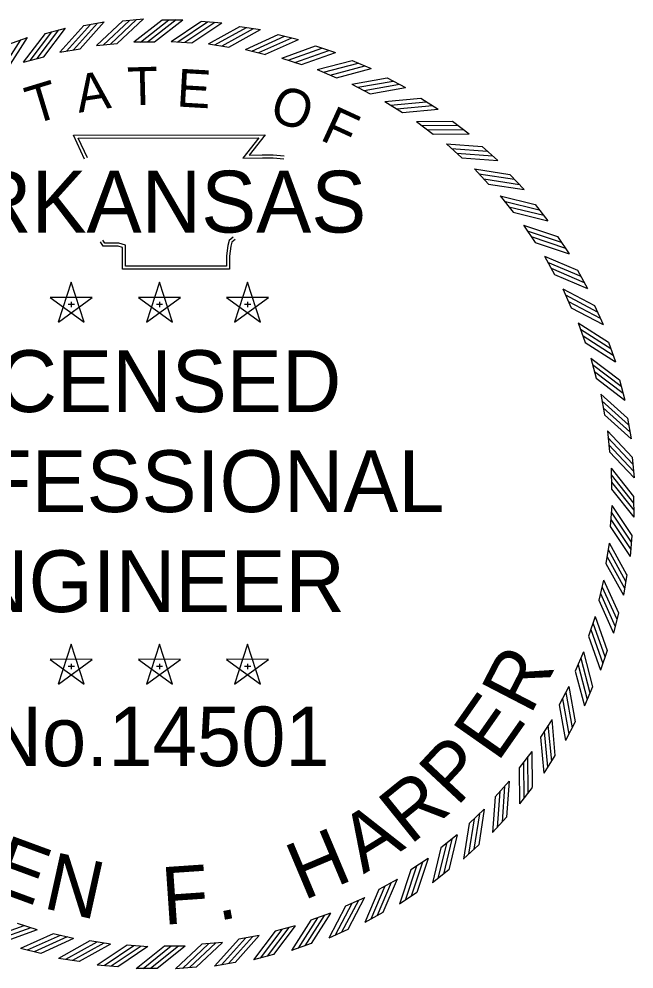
# Model space of a CAD drawing. Extents: x 16 to 1228740, y 11 to 152440.
# Drawn here: x 17.7474 to 17.8589, y 10.8144 to 10.9865 of the extents above; entities that cross this region are included whole.
import ezdxf

# ---------------------------------------------------------------- set-up
doc = ezdxf.new("R2010")
doc.units = 0
doc.layers.add('STAMP_FRED', color=7, linetype='Continuous')

msp = doc.modelspace()

# ---------------------------------------------------------------- linework, layer by layer
at = {"layer": 'STAMP_FRED'}
for p, q in [((17.75911, 10.98533), (17.76283, 10.98598)), ((17.76617, 10.98617), (17.76992, 10.98652)), ((17.77331, 10.98638), (17.77708, 10.98638)), ((17.78037, 10.9861), (17.78413, 10.98582)), ((17.75215, 10.9839), (17.7558, 10.98486)), ((17.78742, 10.98518), (17.79114, 10.9846)), ((17.74533, 10.98191), (17.74888, 10.98317)), ((17.79436, 10.98369), (17.79803, 10.9828)), ((17.75474, 10.98048), (17.75847, 10.98114)), ((17.76141, 10.9817), (17.76518, 10.98205)), ((17.76816, 10.98237), (17.77194, 10.98237)), ((17.77494, 10.98247), (17.77871, 10.9822)), ((17.78171, 10.98202), (17.78544, 10.98143)), ((17.78842, 10.98101), (17.79209, 10.98011)), ((17.80116, 10.98163), (17.80474, 10.98044)), ((17.7482, 10.97872), (17.75185, 10.97968)), ((17.79502, 10.97945), (17.7986, 10.97825)), ((17.80777, 10.97901), (17.81124, 10.97753)), ((17.80146, 10.97734), (17.80494, 10.97586)), ((17.81414, 10.97586), (17.81747, 10.97409)), ((17.80772, 10.97472), (17.81106, 10.97295)), ((17.81373, 10.97158), (17.81691, 10.96955)), ((17.82023, 10.97219), (17.8234, 10.97016)), ((17.81946, 10.96796), (17.82247, 10.96567)), ((17.82599, 10.96803), (17.82898, 10.96574)), ((17.82488, 10.96388), (17.82768, 10.96135)), ((17.83139, 10.96341), (17.83418, 10.96088)), ((17.82994, 10.95937), (17.83253, 10.95661)), ((17.83639, 10.95836), (17.83896, 10.95561)), ((17.83461, 10.95445), (17.83696, 10.95149)), ((17.84095, 10.95291), (17.84329, 10.94996)), ((17.83886, 10.94916), (17.84096, 10.94602)), ((17.84505, 10.94711), (17.84714, 10.94397)), ((17.84266, 10.94354), (17.84449, 10.94024)), ((17.84866, 10.94098), (17.85048, 10.93769)), ((17.75683, 10.93882), (17.75448, 10.93158)), ((17.75918, 10.93158), (17.75684, 10.93882)), ((17.77283, 10.93882), (17.77047, 10.93158)), ((17.77518, 10.93158), (17.77283, 10.93882)), ((17.78882, 10.93882), (17.78646, 10.93158)), ((17.79117, 10.93158), (17.78882, 10.93882)), ((17.76064, 10.93605), (17.75303, 10.93606)), ((17.77663, 10.93605), (17.76902, 10.93606)), ((17.79262, 10.93605), (17.78501, 10.93606)), ((17.84598, 10.93763), (17.84753, 10.93419)), ((17.75303, 10.93605), (17.75919, 10.93157)), ((17.75449, 10.93158), (17.76065, 10.93605)), ((17.75629, 10.93484), (17.75742, 10.93484)), ((17.75684, 10.93524), (17.75684, 10.93429)), ((17.76902, 10.93605), (17.77518, 10.93157)), ((17.77048, 10.93158), (17.77664, 10.93605)), ((17.77228, 10.93484), (17.77341, 10.93484)), ((17.77283, 10.93524), (17.77283, 10.93429)), ((17.78501, 10.93605), (17.79117, 10.93157)), ((17.78647, 10.93158), (17.79263, 10.93605)), ((17.78827, 10.93484), (17.78941, 10.93484)), ((17.78882, 10.93524), (17.78882, 10.93429)), ((17.85175, 10.93458), (17.85329, 10.93115)), ((17.8488, 10.93146), (17.85006, 10.9279)), ((17.85429, 10.92795), (17.85555, 10.9244)), ((17.8511, 10.92509), (17.85206, 10.92143)), ((17.85629, 10.92113), (17.85725, 10.91748)), ((17.85287, 10.91854), (17.85352, 10.91482)), ((17.85771, 10.91417), (17.85837, 10.91046)), ((17.85409, 10.91187), (17.85443, 10.9081)), ((17.85855, 10.90711), (17.8589, 10.90336)), ((17.85475, 10.90512), (17.85479, 10.90134)), ((17.85881, 10.90001), (17.85885, 10.89624)), ((17.85486, 10.89834), (17.85458, 10.89457)), ((17.8544, 10.89157), (17.85382, 10.88784)), ((17.85848, 10.89291), (17.8582, 10.88915)), ((17.85339, 10.88486), (17.8525, 10.88119)), ((17.85757, 10.88586), (17.85698, 10.88214)), ((17.85183, 10.87827), (17.85064, 10.87468)), ((17.85607, 10.87892), (17.85518, 10.87525)), ((17.75683, 10.87325), (17.75448, 10.86602)), ((17.75918, 10.86602), (17.75684, 10.87326)), ((17.77283, 10.87325), (17.77047, 10.86602)), ((17.77518, 10.86602), (17.77283, 10.87326)), ((17.78882, 10.87325), (17.78646, 10.86602)), ((17.79117, 10.86602), (17.78882, 10.87326)), ((17.84973, 10.87182), (17.84824, 10.86834)), ((17.85401, 10.87212), (17.85282, 10.86854)), ((17.76064, 10.87049), (17.75303, 10.8705)), ((17.75303, 10.87049), (17.75919, 10.86601)), ((17.75449, 10.86602), (17.76065, 10.87049)), ((17.75629, 10.86927), (17.75742, 10.86927)), ((17.75684, 10.86968), (17.75684, 10.86873)), ((17.77663, 10.87049), (17.76902, 10.8705)), ((17.76902, 10.87049), (17.77518, 10.86601)), ((17.77048, 10.86602), (17.77664, 10.87049)), ((17.77228, 10.86927), (17.77341, 10.86927)), ((17.77283, 10.86968), (17.77283, 10.86873)), ((17.79262, 10.87049), (17.78501, 10.8705)), ((17.78501, 10.87049), (17.79117, 10.86601)), ((17.78647, 10.86602), (17.79263, 10.87049)), ((17.78827, 10.86927), (17.78941, 10.86927)), ((17.78882, 10.86968), (17.78882, 10.86873)), ((17.8471, 10.86557), (17.84533, 10.86223)), ((17.85139, 10.86551), (17.84991, 10.86204)), ((17.84397, 10.85955), (17.84193, 10.85637)), ((17.84824, 10.85914), (17.84648, 10.85581)), ((17.84035, 10.85382), (17.83805, 10.85081)), ((17.84457, 10.85306), (17.84254, 10.84988)), ((17.83626, 10.8484), (17.83373, 10.8456)), ((17.84041, 10.84729), (17.83812, 10.8443)), ((17.83175, 10.84334), (17.82899, 10.84076)), ((17.83579, 10.84189), (17.83326, 10.8391)), ((17.82683, 10.83867), (17.82387, 10.83632)), ((17.83074, 10.8369), (17.82799, 10.83432)), ((17.82155, 10.83442), (17.8184, 10.83233)), ((17.8253, 10.83233), (17.82234, 10.82999)), ((17.81593, 10.83062), (17.81262, 10.8288)), ((17.81949, 10.82823), (17.81635, 10.82614)), ((17.81001, 10.8273), (17.80657, 10.82576)), ((17.80385, 10.82448), (17.80029, 10.82322)), ((17.81337, 10.82462), (17.81007, 10.8228)), ((17.75065, 10.82145), (17.74706, 10.82265)), ((17.75725, 10.81989), (17.75358, 10.82078)), ((17.79747, 10.82218), (17.79381, 10.82122)), ((17.80697, 10.82154), (17.80353, 10.81999)), ((17.76395, 10.81888), (17.76022, 10.81947)), ((17.78425, 10.81919), (17.78049, 10.81885)), ((17.79092, 10.82042), (17.7872, 10.81976)), ((17.7513, 10.81721), (17.74764, 10.8181)), ((17.77072, 10.81842), (17.76695, 10.8187)), ((17.7775, 10.81853), (17.77372, 10.81849)), ((17.80033, 10.81899), (17.79678, 10.81773)), ((17.75825, 10.81572), (17.75452, 10.8163)), ((17.78655, 10.81557), (17.78284, 10.81492)), ((17.79351, 10.81699), (17.78987, 10.81603)), ((17.7653, 10.8148), (17.76154, 10.81508)), ((17.77239, 10.81447), (17.76862, 10.81444)), ((17.7795, 10.81473), (17.77574, 10.81438))]:
    msp.add_line(p, q, dxfattribs=at)
for points in [[(17.75846, 10.98114), (17.76283, 10.98599)], [(17.76141, 10.9817), (17.76616, 10.98617)], [(17.76262, 10.9818), (17.76737, 10.98627)], [(17.76392, 10.98195), (17.76868, 10.98642)], [(17.76517, 10.98205), (17.76993, 10.98652)], [(17.76816, 10.98237), (17.7733, 10.98638)], [(17.76937, 10.98235), (17.77452, 10.98637)], [(17.77068, 10.98238), (17.77583, 10.9864)], [(17.77194, 10.98237), (17.77708, 10.98638)], [(17.77494, 10.98247), (17.78036, 10.98609)], [(17.77615, 10.98237), (17.78157, 10.98599)], [(17.75063, 10.97937), (17.75458, 10.98456)], [(17.75185, 10.97968), (17.7558, 10.98487)], [(17.75474, 10.98048), (17.75911, 10.98532)], [(17.75594, 10.98068), (17.76031, 10.98552)], [(17.75722, 10.98093), (17.76159, 10.98578)], [(17.77746, 10.9823), (17.78288, 10.98593)], [(17.77871, 10.9822), (17.78413, 10.98582)], [(17.78171, 10.98202), (17.78741, 10.98518)], [(17.7829, 10.98182), (17.78861, 10.98498)], [(17.7842, 10.98164), (17.78991, 10.98481)], [(17.78544, 10.98144), (17.79114, 10.9846)], [(17.74419, 10.97727), (17.7477, 10.98276)], [(17.74537, 10.97768), (17.74889, 10.98317)], [(17.74819, 10.97871), (17.75215, 10.9839)], [(17.74937, 10.97901), (17.75332, 10.9842)], [(17.78841, 10.98101), (17.79436, 10.98369)], [(17.78959, 10.98071), (17.79553, 10.98339)], [(17.79087, 10.98043), (17.79681, 10.98311)], [(17.79208, 10.98012), (17.79803, 10.9828)], [(17.79501, 10.97944), (17.80116, 10.98163)], [(17.79616, 10.97905), (17.80231, 10.98123)], [(17.79741, 10.97866), (17.80356, 10.98084)], [(17.7986, 10.97826), (17.80475, 10.98044)], [(17.80146, 10.97734), (17.80777, 10.97901)], [(17.80257, 10.97686), (17.80888, 10.97852)], [(17.80379, 10.97637), (17.81009, 10.97803)], [(17.80494, 10.97586), (17.81124, 10.97753)], [(17.80771, 10.97472), (17.81413, 10.97586)], [(17.80878, 10.97414), (17.8152, 10.97528)], [(17.80995, 10.97355), (17.81637, 10.97469)], [(17.81105, 10.97295), (17.81748, 10.97409)], [(17.81372, 10.97158), (17.82022, 10.97219)], [(17.81474, 10.97092), (17.82123, 10.97152)], [(17.81586, 10.97024), (17.82235, 10.97084)], [(17.81691, 10.96955), (17.8234, 10.97016)], [(17.81946, 10.96796), (17.82598, 10.96803)], [(17.82042, 10.96722), (17.82694, 10.96728)], [(17.75926, 10.96115), (17.75725, 10.9655), (17.79202, 10.96552), (17.78912, 10.96187), (17.79148, 10.9619), (17.79345, 10.96193), (17.79542, 10.96171)], [(17.82147, 10.96645), (17.828, 10.96651)], [(17.82247, 10.96567), (17.82899, 10.96574)], [(17.75976, 10.96138), (17.75811, 10.96495), (17.79088, 10.96497), (17.78796, 10.96131), (17.79149, 10.96135), (17.79343, 10.96138), (17.79536, 10.96117)], [(17.82487, 10.96388), (17.83138, 10.96341)], [(17.82577, 10.96306), (17.83227, 10.96259)], [(17.82676, 10.9622), (17.83326, 10.96173)], [(17.82768, 10.96135), (17.83419, 10.96088)], [(17.82994, 10.95937), (17.83638, 10.95836)], [(17.83076, 10.95848), (17.8372, 10.95747)], [(17.83167, 10.95754), (17.83812, 10.95653)], [(17.83252, 10.95662), (17.83897, 10.95561)], [(17.83461, 10.95445), (17.84095, 10.95291)], [(17.83535, 10.95349), (17.84169, 10.95196)], [(17.83619, 10.95249), (17.84253, 10.95095)], [(17.83696, 10.95149), (17.8433, 10.94996)], [(17.83885, 10.94917), (17.84504, 10.94711)], [(17.83952, 10.94815), (17.84571, 10.94609)], [(17.78654, 10.94658), (17.78595, 10.9461), (17.78575, 10.94538), (17.78556, 10.94357), (17.78556, 10.94117), (17.76615, 10.94117), (17.76615, 10.94441), (17.76615, 10.94514), (17.76536, 10.94538), (17.7626, 10.94538), (17.76211, 10.94612)], [(17.7862, 10.94701), (17.78547, 10.94641), (17.78521, 10.94548), (17.78501, 10.9436), (17.78501, 10.94172), (17.7667, 10.94172), (17.7667, 10.94441), (17.7667, 10.94554), (17.76544, 10.94593), (17.7629, 10.94593), (17.76257, 10.94643)], [(17.84027, 10.94708), (17.84646, 10.94502)], [(17.84096, 10.94602), (17.84715, 10.94397)], [(17.84265, 10.94355), (17.84865, 10.94099)], [(17.84323, 10.94248), (17.84923, 10.93992)], [(17.84389, 10.94135), (17.84989, 10.93879)], [(17.84449, 10.94024), (17.85049, 10.93768)], [(17.84597, 10.93763), (17.85174, 10.93459)], [(17.84646, 10.93652), (17.85223, 10.93348)], [(17.84702, 10.93534), (17.85279, 10.93229)], [(17.84753, 10.93419), (17.8533, 10.93114)], [(17.84879, 10.93147), (17.85429, 10.92796)], [(17.84919, 10.93032), (17.85468, 10.92681)], [(17.84965, 10.92909), (17.85515, 10.92558)], [(17.85006, 10.92791), (17.85556, 10.9244)], [(17.8511, 10.92509), (17.85628, 10.92113)], [(17.85139, 10.92391), (17.85658, 10.91996)], [(17.85175, 10.92265), (17.85694, 10.9187)], [(17.85206, 10.92144), (17.85725, 10.91748)], [(17.85286, 10.91854), (17.85771, 10.91417)], [(17.85306, 10.91734), (17.85791, 10.91298)], [(17.85332, 10.91606), (17.85816, 10.91169)], [(17.85352, 10.91482), (17.85837, 10.91045)], [(17.85408, 10.91187), (17.85855, 10.90712)], [(17.85418, 10.91066), (17.85865, 10.90591)], [(17.85433, 10.90936), (17.8588, 10.90461)], [(17.85444, 10.90811), (17.8589, 10.90336)], [(17.85475, 10.90512), (17.85881, 10.90002)], [(17.85475, 10.90391), (17.85881, 10.8988)], [(17.85479, 10.9026), (17.85885, 10.89749)], [(17.85479, 10.90134), (17.85885, 10.89624)], [(17.85485, 10.89834), (17.85848, 10.89292)], [(17.85475, 10.89713), (17.85838, 10.89171)], [(17.85469, 10.89582), (17.85831, 10.8904)], [(17.85458, 10.89457), (17.85821, 10.88915)], [(17.8544, 10.89158), (17.85756, 10.88587)], [(17.8542, 10.89038), (17.85736, 10.88467)], [(17.85403, 10.88908), (17.85719, 10.88338)], [(17.85382, 10.88784), (17.85698, 10.88214)], [(17.85339, 10.88487), (17.85607, 10.87892)], [(17.85309, 10.88369), (17.85577, 10.87775)], [(17.8525, 10.8812), (17.85518, 10.87525)], [(17.85281, 10.88241), (17.85549, 10.87647)], [(17.85183, 10.87827), (17.85401, 10.87212)], [(17.85105, 10.87587), (17.85323, 10.86972)], [(17.85143, 10.87712), (17.85361, 10.87098)], [(17.85064, 10.87468), (17.85282, 10.86854)], [(17.84924, 10.87071), (17.8509, 10.86441)], [(17.84973, 10.87182), (17.85139, 10.86552)], [(17.84875, 10.8695), (17.85042, 10.86319)], [(17.84825, 10.86835), (17.84991, 10.86204)], [(17.8471, 10.86557), (17.84824, 10.85915)], [(17.84652, 10.8645), (17.84766, 10.85808)], [(17.84534, 10.86223), (17.84648, 10.85581)], [(17.84594, 10.86333), (17.84707, 10.85691)], [(17.84397, 10.85956), (17.84457, 10.85306)], [(17.84262, 10.85742), (17.84323, 10.85093)], [(17.8433, 10.85854), (17.84391, 10.85205)], [(17.84193, 10.85637), (17.84254, 10.84988)], [(17.84035, 10.85382), (17.84041, 10.8473)], [(17.83883, 10.85181), (17.8389, 10.84528)], [(17.8396, 10.85287), (17.83967, 10.84634)], [(17.83806, 10.85082), (17.83812, 10.84429)], [(17.83627, 10.84841), (17.83579, 10.8419)], [(17.83544, 10.84751), (17.83497, 10.84101)], [(17.83374, 10.8456), (17.83326, 10.83909)], [(17.83459, 10.84652), (17.83411, 10.84002)], [(17.83175, 10.84335), (17.83074, 10.8369)], [(17.82992, 10.84161), (17.82891, 10.83516)], [(17.83086, 10.84252), (17.82985, 10.83608)], [(17.829, 10.84076), (17.82799, 10.83431)], [(17.82683, 10.83868), (17.8253, 10.83234)], [(17.82388, 10.83632), (17.82234, 10.82998)], [(17.82487, 10.83709), (17.82333, 10.83076)], [(17.82588, 10.83793), (17.82434, 10.83159)], [(17.81946, 10.83301), (17.8174, 10.82682)], [(17.82053, 10.83376), (17.81848, 10.82757)], [(17.82155, 10.83443), (17.81949, 10.82824)], [(17.81841, 10.83233), (17.81635, 10.82614)], [(17.81373, 10.82939), (17.81117, 10.82339)], [(17.81486, 10.83005), (17.8123, 10.82405)], [(17.81593, 10.83063), (17.81337, 10.82463)], [(17.81263, 10.8288), (17.81007, 10.8228)], [(17.80772, 10.82626), (17.80468, 10.82049)], [(17.80891, 10.82682), (17.80586, 10.82105)], [(17.81002, 10.82731), (17.80697, 10.82154)], [(17.80385, 10.82449), (17.80034, 10.81899)], [(17.80657, 10.82575), (17.80353, 10.81999)], [(17.80029, 10.82322), (17.79678, 10.81773)], [(17.80148, 10.82363), (17.79797, 10.81813)], [(17.8027, 10.82409), (17.79919, 10.8186)], [(17.74825, 10.82223), (17.74211, 10.82005)], [(17.74951, 10.82185), (17.74336, 10.81967)], [(17.75065, 10.82145), (17.74451, 10.81927)], [(17.75358, 10.82078), (17.74763, 10.8181)], [(17.79382, 10.82122), (17.78987, 10.81603)], [(17.79504, 10.82153), (17.79108, 10.81634)], [(17.7963, 10.82189), (17.79234, 10.8167)], [(17.79747, 10.82219), (17.79352, 10.817)], [(17.7548, 10.82047), (17.74885, 10.81779)], [(17.75608, 10.82019), (17.75013, 10.81751)], [(17.75725, 10.81989), (17.75131, 10.81721)], [(17.76023, 10.81946), (17.75452, 10.8163)], [(17.76146, 10.81926), (17.75576, 10.81609)], [(17.76276, 10.81908), (17.75706, 10.81592)], [(17.78304, 10.8191), (17.77829, 10.81463)], [(17.78425, 10.8192), (17.7795, 10.81473)], [(17.7872, 10.81976), (17.78284, 10.81491)], [(17.78844, 10.81996), (17.78407, 10.81512)], [(17.78973, 10.82022), (17.78536, 10.81538)], [(17.79092, 10.82042), (17.78656, 10.81558)], [(17.76396, 10.81888), (17.75825, 10.81572)], [(17.76696, 10.8187), (17.76153, 10.81507)], [(17.76821, 10.81859), (17.76278, 10.81497)], [(17.76952, 10.81853), (17.76409, 10.8149)], [(17.77073, 10.81843), (17.7653, 10.8148)], [(17.77373, 10.81849), (17.76862, 10.81443)], [(17.77498, 10.81849), (17.76988, 10.81443)], [(17.77629, 10.81853), (17.77119, 10.81447)], [(17.77751, 10.81853), (17.7724, 10.81447)], [(17.78049, 10.81885), (17.77574, 10.81438)], [(17.78174, 10.81895), (17.77699, 10.81448)]]:
    msp.add_lwpolyline(points, dxfattribs=at)

# ---------------------------------------------------------------- texts
for s, height, rotation, p in [('T', 0.00686, 1.4789, (17.76706, 10.97088)), ('E', 0.00686, 356.672, (17.77584, 10.97068)), ('A', 0.00686, 8.6788, (17.7582, 10.96952)), ('T', 0.00686, 16.9015, (17.74988, 10.96735)), ('O', 0.00686, 341.2218, (17.79249, 10.96832)), ('F', 0.00686, 335.3628, (17.80173, 10.96471)), ('R', 0.01042, 62.6418, (17.84011, 10.86023)), ('E', 0.01042, 54.981, (17.83415, 10.85167)), ('P', 0.01042, 46.9554, (17.82675, 10.84364)), ('R', 0.01042, 38.9298, (17.81829, 10.83672)), ('A', 0.01042, 31.6338, (17.80983, 10.83151)), ('H', 0.01042, 22.8786, (17.79892, 10.82673)), ('E', 0.01042, 339.8321, (17.74168, 10.82902)), ('N', 0.01042, 347.4929, (17.75149, 10.82546)), ('F', 0.01042, 3.9089, (17.77356, 10.82238)), ('.', 0.01042, 11.205, (17.78347, 10.82306))]:
    msp.add_text(s, height=height, rotation=rotation, dxfattribs=at).set_placement(p)
for s, height, p in [('ARKANSAS', 0.011193, (17.72883, 10.94783)), ('LICENSED', 0.011193, (17.73096, 10.9153)), ('PROFESSIONAL', 0.0111934, (17.70804, 10.89717)), ('ENGINEER', 0.011193, (17.7283, 10.87905)), ('No.14501', 0.010794, (17.7411, 10.85114))]:
    msp.add_text(s, height=height, dxfattribs=at).set_placement(p)

doc.saveas('drawing.dxf')
